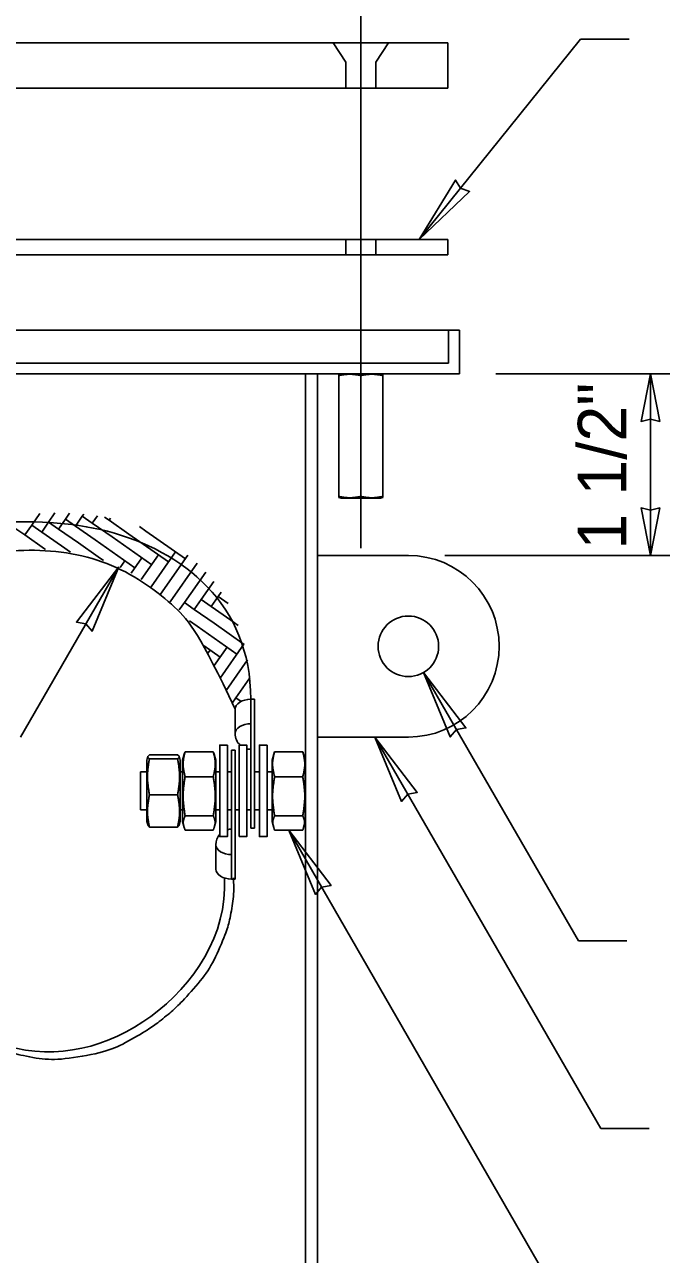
# Model space of a CAD drawing. Extents: x 99862 to 103680, y 99470 to 102076.
# Drawn here: x 100436.1 to 100646.6, y 100208.5 to 100614.8 of the extents above; entities that cross this region are included whole.
import ezdxf

# ---------------------------------------------------------------- set-up
doc = ezdxf.new("R2010")
doc.units = 0
for name, color, linetype in [('Level 1', 7, 'Continuous'), ('Level 10', 7, 'Continuous'), ('Level 11', 7, 'Continuous'), ('Level 13', 7, 'Continuous'), ('Level 15', 7, 'Continuous'), ('Level 16', 7, 'Continuous'), ('Level 2', 7, 'Continuous'), ('Level 20', 7, 'Continuous'), ('Level 6', 7, 'Continuous'), ('Level 9', 7, 'Continuous')]:
    doc.layers.add(name, color=color, linetype=linetype)

msp = doc.modelspace()

# ---------------------------------------------------------------- linework, layer by layer
at = {"layer": 'Level 1'}
for p, q in [((100015.12, 100513.87), (100579.84, 100513.87)), ((100576.28, 100502.97), (100576.28, 100513.87)), ((100579.84, 100499.41), (100579.84, 100513.87)), ((100018.69, 100502.97), (100576.28, 100502.97)), ((100015.12, 100499.41), (100579.84, 100499.41)), ((100528.98, 100139.35), (100528.98, 100499.41)), ((100532.98, 100135.35), (100532.98, 100499.41))]:
    msp.add_line(p, q, dxfattribs=at)
at = {"layer": 'Level 10'}
for p, q in [((100540.75, 100499.41), (100539.99, 100499.2)), ((100540.75, 100499.41), (100539.99, 100499.2)), ((100540.75, 100499.41), (100539.99, 100499.2)), ((100540.75, 100499.41), (100539.99, 100499.2)), ((100539.99, 100458.9), (100539.99, 100498.89)), ((100540.75, 100499.41), (100547.25, 100499.41)), ((100547.25, 100499.41), (100553.75, 100499.41)), ((100547.25, 100458.9), (100547.25, 100498.89)), ((100554.51, 100499.2), (100553.75, 100499.41)), ((100554.51, 100499.2), (100553.75, 100499.41)), ((100554.51, 100499.2), (100553.75, 100499.41)), ((100554.51, 100499.2), (100553.75, 100499.41)), ((100554.51, 100458.9), (100554.51, 100498.89)), ((100539.99, 100458.59), (100540.75, 100458.37)), ((100540.75, 100458.37), (100553.75, 100458.37)), ((100553.75, 100458.37), (100554.51, 100458.59)), ((100476.9, 100373.08), (100476.55, 100371.82)), ((100477.37, 100373.61), (100476.9, 100373.06)), ((100477.37, 100373.61), (100486.71, 100373.61)), ((100477.37, 100372.28), (100486.71, 100372.28)), ((100486.71, 100373.61), (100487.18, 100373.07)), ((100487.53, 100371.82), (100487.18, 100373.08)), ((100488.9, 100373.83), (100488.34, 100371.82)), ((100488.9, 100373.81), (100489.16, 100374.6)), ((100489.16, 100374.6), (100498.5, 100374.6)), ((100498.76, 100373.81), (100498.5, 100374.6)), ((100499.32, 100371.82), (100498.76, 100373.83)), ((100518.48, 100373.83), (100517.92, 100371.81)), ((100518.48, 100373.81), (100518.74, 100374.6)), ((100518.74, 100374.6), (100528.08, 100374.6)), ((100528.34, 100373.81), (100528.08, 100374.6)), ((100528.9, 100371.81), (100528.34, 100373.83)), ((100476.55, 100367.91), (100474.48, 100367.91)), ((100488.34, 100367.91), (100487.53, 100367.91)), ((100500.65, 100367.91), (100499.32, 100367.91)), ((100503.15, 100367.91), (100504.52, 100367.91)), ((100512.19, 100367.91), (100513.76, 100367.91)), ((100516.26, 100367.91), (100517.92, 100367.91)), ((100489.16, 100366.34), (100498.5, 100366.34)), ((100518.74, 100366.34), (100528.08, 100366.34)), ((100477.37, 100360.33), (100486.71, 100360.33)), ((100474.48, 100355.41), (100476.55, 100355.41)), ((100487.53, 100355.41), (100488.34, 100355.41)), ((100499.32, 100355.41), (100500.65, 100355.41)), ((100504.52, 100355.41), (100503.15, 100355.41)), ((100507.07, 100355.41), (100505.77, 100355.41)), ((100510.94, 100355.41), (100509.57, 100355.41)), ((100513.76, 100355.41), (100512.19, 100355.41)), ((100517.92, 100355.41), (100516.26, 100355.41)), ((100476.55, 100351.5), (100476.91, 100350.24)), ((100487.18, 100350.24), (100487.53, 100351.5)), ((100488.34, 100351.5), (100488.9, 100349.5)), ((100489.16, 100353.4), (100498.5, 100353.4)), ((100498.76, 100349.5), (100499.32, 100351.5)), ((100517.92, 100351.5), (100518.48, 100349.5)), ((100518.74, 100353.4), (100528.08, 100353.4)), ((100528.34, 100349.5), (100528.9, 100351.5)), ((100477.37, 100349.7), (100476.9, 100350.25)), ((100477.37, 100349.7), (100486.71, 100349.71)), ((100486.71, 100349.71), (100487.18, 100350.25)), ((100489.16, 100348.72), (100498.5, 100348.72)), ((100518.74, 100348.72), (100528.08, 100348.72))]:
    msp.add_line(p, q, dxfattribs=at)
for centre, major_axis, start_param, end_param in [((100476.55, 100361.66), (0, 10.16), 0.00006, 0.625296), ((100487.53, 100361.66), (0, 10.16), 6.283125, 6.908482), ((100487.53, 100361.66), (0, 10.16), 5.37533, 6.283125), ((100488.34, 100361.66), (0, 10.16), 0.00006, 1.20535), ((100499.32, 100361.66), (0, 10.16), 6.283125, 7.488535), ((100499.32, 100361.66), (0, 10.16), 5.37528, 6.283125), ((100517.92, 100361.66), (0, 10.16), 0.00006, 1.20535), ((100528.9, 100361.66), (0, 10.16), 6.283125, 7.488535), ((100528.9, 100361.66), (0, 10.16), 5.37528, 6.283125), ((100474.48, 100361.66), (0, -6.25), 3.141593, 5.657889), ((100474.48, 100361.66), (0, -6.25), 0, 3.141593), ((100476.55, 100361.66), (0, 10.16), 0.625296, 3.141532), ((100487.53, 100361.66), (0, 10.16), 0.625296, 3.141653), ((100487.53, 100361.66), (0, -6.25), 3.141593, 6.283185), ((100499.32, 100361.66), (0, -6.25), 3.123167, 3.141593), ((100499.32, 100361.66), (0, -6.25), 3.141593, 6.283185), ((100528.9, 100361.66), (0, -6.25), 3.123167, 3.141593), ((100528.9, 100361.66), (0, -6.25), 3.141593, 6.283185), ((100488.34, 100361.66), (0, 10.16), 1.20535, 3.141532), ((100499.32, 100361.66), (0, 10.16), 1.20535, 3.141653), ((100517.92, 100361.66), (0, 10.16), 1.20535, 3.141532), ((100528.9, 100361.66), (0, 10.16), 1.20535, 3.141653), ((100474.48, 100361.66), (0, -6.25), 5.657889, 6.283185), ((100476.55, 100361.66), (0, -6.25), 0, 0.013106), ((100487.53, 100361.66), (0, 10.16), 3.141653, 4.049582), ((100487.53, 100361.66), (0, -6.25), 0, 0.013106), ((100488.34, 100361.66), (0, -6.25), 0, 0.007018), ((100499.32, 100361.66), (0, 10.16), 3.141653, 4.049537), ((100499.32, 100361.66), (0, -6.25), 6.283185, 6.303313), ((100528.9, 100361.66), (0, 10.16), 3.141653, 4.049537), ((100528.9, 100361.66), (0, -6.25), 6.283185, 6.303313)]:
    msp.add_ellipse(centre, major_axis=major_axis, ratio=0.000017, start_param=start_param, end_param=end_param, dxfattribs=at)
for points in [[(100547.25, 100498.89), (100544.83, 100499.31), (100542.41, 100499.3), (100539.99, 100498.89)], [(100539.99, 100498.89), (100539.99, 100498.99), (100539.99, 100499.09), (100539.99, 100499.19)], [(100554.51, 100498.89), (100552.09, 100499.31), (100549.67, 100499.3), (100547.25, 100498.89)], [(100554.51, 100499.2), (100554.51, 100499.09), (100554.51, 100498.99), (100554.51, 100498.89)], [(100539.99, 100458.9), (100539.99, 100458.8), (100539.99, 100458.69), (100539.99, 100458.59)], [(100547.25, 100458.9), (100544.83, 100458.47), (100542.41, 100458.48), (100539.99, 100458.9)], [(100554.51, 100458.9), (100552.09, 100458.47), (100549.67, 100458.48), (100547.25, 100458.9)], [(100554.51, 100458.59), (100554.51, 100458.69), (100554.51, 100458.79), (100554.51, 100458.9)], [(100477.37, 100372.28), (100476.7, 100368.3), (100476.72, 100364.31), (100477.37, 100360.33)], [(100476.9, 100373.06), (100476.8, 100372.8), (100477.08, 100372.54), (100477.37, 100372.28)], [(100487.18, 100373.07), (100487.28, 100372.8), (100487, 100372.54), (100486.71, 100372.28)], [(100486.71, 100372.28), (100487.38, 100368.3), (100487.36, 100364.31), (100486.71, 100360.33)], [(100489.16, 100374.6), (100488.49, 100371.85), (100488.51, 100369.09), (100489.16, 100366.34)], [(100498.5, 100374.6), (100499.17, 100371.85), (100499.15, 100369.1), (100498.5, 100366.34)], [(100518.74, 100374.6), (100518.07, 100371.84), (100518.09, 100369.09), (100518.74, 100366.34)], [(100528.08, 100374.6), (100528.75, 100371.85), (100528.73, 100369.09), (100528.08, 100366.34)], [(100489.16, 100366.34), (100488.49, 100362.03), (100488.51, 100357.72), (100489.16, 100353.4)], [(100498.5, 100366.34), (100499.17, 100362.03), (100499.15, 100357.72), (100498.5, 100353.4)], [(100518.74, 100366.34), (100518.07, 100362.03), (100518.09, 100357.71), (100518.74, 100353.4)], [(100528.08, 100366.34), (100528.75, 100362.03), (100528.73, 100357.71), (100528.08, 100353.4)], [(100477.37, 100360.33), (100476.75, 100356.81), (100476.68, 100353.23), (100477.37, 100349.7)], [(100486.71, 100360.33), (100487.33, 100356.81), (100487.4, 100353.23), (100486.71, 100349.71)], [(100489.16, 100353.4), (100488.64, 100352.11), (100488.49, 100350.81), (100488.9, 100349.51)], [(100498.5, 100353.4), (100499.02, 100352.11), (100499.17, 100350.81), (100498.76, 100349.51)], [(100518.74, 100353.4), (100518.22, 100352.11), (100518.07, 100350.81), (100518.48, 100349.51)], [(100528.08, 100353.4), (100528.6, 100352.11), (100528.75, 100350.81), (100528.34, 100349.51)], [(100488.9, 100349.51), (100488.98, 100349.25), (100489.07, 100348.98), (100489.16, 100348.72)], [(100498.76, 100349.51), (100498.67, 100349.25), (100498.59, 100348.98), (100498.5, 100348.72)], [(100518.48, 100349.51), (100518.57, 100349.24), (100518.65, 100348.98), (100518.74, 100348.72)], [(100528.34, 100349.51), (100528.26, 100349.24), (100528.17, 100348.98), (100528.08, 100348.72)]]:
    msp.add_open_spline(points, degree=2, dxfattribs=at)
at = {"layer": 'Level 11'}
for p, q in [((100441.17, 100453.31), (100438.48, 100449.47)), ((100446.16, 100453.46), (100444.05, 100450.45)), ((100450.99, 100453.38), (100449.62, 100451.43)), ((100455.66, 100453.09), (100455.19, 100452.41)), ((100458.47, 100450.12), (100460.16, 100452.53)), ((100436.19, 100446.19), (100432.91, 100448.48)), ((100436.19, 100446.19), (100438.48, 100449.47)), ((100441.76, 100447.17), (100438.48, 100449.47)), ((100441.76, 100447.17), (100444.05, 100450.45)), ((100447.33, 100448.15), (100444.05, 100450.45)), ((100447.33, 100448.15), (100449.62, 100451.43)), ((100452.9, 100449.14), (100449.62, 100451.43)), ((100452.9, 100449.14), (100455.19, 100452.41)), ((100452.9, 100449.14), (100459.45, 100444.55)), ((100458.47, 100450.12), (100455.19, 100452.41)), ((100458.47, 100450.12), (100465.02, 100445.53)), ((100458.47, 100450.12), (100458.47, 100450.12)), ((100464.04, 100451.1), (100462.57, 100452.13)), ((100464.04, 100451.1), (100464.49, 100451.75)), ((100464.04, 100451.1), (100470.59, 100446.51)), ((100474.09, 100448.94), (100476.16, 100447.49)), ((100436.19, 100446.19), (100442.74, 100441.6)), ((100441.76, 100447.17), (100448.31, 100442.58)), ((100447.33, 100448.15), (100453.88, 100443.57)), ((100472.56, 100435.37), (100459.45, 100444.55)), ((100459.45, 100444.55), (100459.45, 100444.55)), ((100478.13, 100436.35), (100465.02, 100445.53)), ((100483.7, 100437.33), (100470.59, 100446.51)), ((100489.27, 100438.32), (100476.16, 100447.49)), ((100443.06, 100441.37), (100442.74, 100441.6)), ((100451.33, 100440.47), (100448.31, 100442.58)), ((100460.43, 100438.98), (100453.88, 100443.57)), ((100485.99, 100440.61), (100477.92, 100429.08)), ((100462.24, 100437.71), (100460.43, 100438.98)), ((100469.28, 100437.66), (100467.72, 100435.43)), ((100474.85, 100438.65), (100471.29, 100433.56)), ((100480.42, 100439.63), (100474.69, 100431.44)), ((100490.12, 100439.54), (100481.09, 100426.64)), ((100493.13, 100436.85), (100484.19, 100424.09)), ((100495.98, 100433.95), (100488.94, 100423.9)), ((100498.64, 100430.78), (100494.51, 100424.88)), ((100492.22, 100421.6), (100494.51, 100424.88)), ((100497.79, 100422.59), (100494.51, 100424.88)), ((100497.79, 100422.59), (100500.08, 100425.86)), ((100501.12, 100427.35), (100500.08, 100425.86)), ((100503.36, 100423.57), (100500.08, 100425.86)), ((100487.23, 100421.45), (100488.94, 100423.9)), ((100492.22, 100421.6), (100488.94, 100423.9)), ((100492.22, 100421.6), (100498.77, 100417.02)), ((100497.79, 100422.59), (100504.34, 100418)), ((100503.36, 100423.57), (100503.39, 100423.61)), ((100503.36, 100423.57), (100503.45, 100423.51)), ((100490.67, 100417.8), (100493.2, 100416.03)), ((100506.31, 100406.86), (100493.2, 100416.03)), ((100508.73, 100410.04), (100498.77, 100417.02)), ((100506.76, 100416.3), (100504.34, 100418)), ((100500.73, 100405.87), (100495.43, 100409.59)), ((100497.46, 100408.17), (100496.71, 100407.1)), ((100503.03, 100409.15), (100498.74, 100403.02)), ((100508.6, 100410.13), (100500.76, 100398.94)), ((100509.83, 100404.91), (100502.75, 100394.8)), ((100510.57, 100399), (100505.98, 100392.44)), ((100504.73, 100390.66), (100505.98, 100392.44)), ((100507.71, 100391.22), (100505.98, 100392.44))]:
    msp.add_line(p, q, dxfattribs=at)
for points in [[(100510.88, 100391.91), (100510.88, 100423.45), (100465.8, 100458.51), (100384.44, 100444.44), (100299.25, 100431.66), (100238.45, 100476.01), (100238.63, 100499.41)], [(100250.4, 100499.41), (100251.03, 100487.36), (100262.3, 100450.41), (100309.58, 100418.45), (100364.95, 100427.4), (100409.25, 100437.62), (100437.58, 100442.78), (100465.99, 100438.02), (100487.69, 100421.82), (100494.02, 100413.33), (100505.7, 100388.64)]]:
    msp.add_open_spline(points, degree=3, dxfattribs=at)
at = {"layer": 'Level 13'}
for p, q in [((100510.88, 100349.28), (100510.88, 100391.91)), ((100510.88, 100391.91), (100512.13, 100391.91)), ((100512.13, 100391.91), (100512.13, 100349.28)), ((100505.7, 100388.64), (100505.7, 100380.58)), ((100504.52, 100375.15), (100505.77, 100375.15)), ((100504.52, 100367.91), (100504.52, 100374.91)), ((100504.52, 100361.95), (100504.52, 100348.41)), ((100505.77, 100348.41), (100505.77, 100361.95)), ((100504.52, 100349.04), (100504.52, 100351.71)), ((100504.52, 100348.17), (100504.52, 100349.04)), ((100504.52, 100339.05), (100504.52, 100348.17)), ((100510.88, 100349.28), (100512.13, 100349.28)), ((100499.33, 100335.79), (100499.33, 100343.85)), ((100504.52, 100345.19), (100504.52, 100332.52)), ((100505.77, 100332.52), (100505.77, 100345.19)), ((100504.52, 100340.59), (100504.52, 100332.52)), ((100504.52, 100332.52), (100505.77, 100332.52))]:
    msp.add_line(p, q, dxfattribs=at)
for points in [[(100503.15, 100376.76), (100500.65, 100376.76), (100500.65, 100346.55), (100503.15, 100346.55)], [(100507.07, 100346.55), (100509.57, 100346.55), (100509.57, 100376.76), (100507.07, 100376.76)], [(100516.26, 100376.76), (100513.75, 100376.76), (100513.75, 100346.55), (100516.26, 100346.55)]]:
    msp.add_lwpolyline(points, close=True, dxfattribs=at)
for centre, start, end in [((100510.88, 100380.58), 179.9981, 227.372), ((100510.88, 100380.58), 255.3387, 269.9976), ((100504.52, 100343.85), 138.2543, 180.0019), ((100504.52, 100343.85), 90.0024, 105.3086)]:
    msp.add_arc(centre, 5.19, start, end, dxfattribs=at)
for centre, major_axis, ratio, start_param, end_param in [((100510.88, 100388.64), (-5.19, 0), 0.628956, 4.712377, 6.283185), ((100510.88, 100380.58), (5.19, 0), 0.628956, 1.570785, 3.141593), ((100504.52, 100361.66), (0, 13.49), 0.000009, 0, 0.189093), ((100504.52, 100361.66), (0, 13.49), 0.000009, 4.733674, 6.283185), ((100505.77, 100361.66), (0, -13.49), 0.000009, 1.592081, 3.14161), ((100504.52, 100361.66), (0, 6.39), 0.000009, 4.03218, 6.283185), ((100504.52, 100361.66), (0, 6.39), 0.000009, 0, 0.210823), ((100504.52, 100361.66), (0, 6.39), 0.000009, 3.141593, 4.03218), ((100504.52, 100356.52), (0, -6.72), 0.000009, 0.774011, 1.405276), ((100504.52, 100361.66), (0, 6.39), 0.000009, 2.934075, 3.141593), ((100504.52, 100343.85), (0, 5.19), 0.000009, 5.697958, 6.283185), ((100504.52, 100361.66), (0, 13.49), 0.000009, 3.141593, 3.330685), ((100504.52, 100341.6), (0, -6.72), 0.000009, 3.246781, 3.347912), ((100504.52, 100361.66), (0, 13.49), 0.000009, 3.016518, 3.141593), ((100504.52, 100341.6), (0, -6.72), 0.000009, 3.347912, 4.148756), ((100504.52, 100343.85), (0, 5.19), 0.000009, 4.03218, 5.697958), ((100505.77, 100361.66), (0, -13.49), 0.000009, 6.283185, 6.472278), ((100505.77, 100341.6), (0, 6.72), 0.000009, 0.105189, 0.206319), ((100505.77, 100341.6), (0, 6.72), 0.000009, 0.206319, 1.007164), ((100504.52, 100343.85), (5.19, 0), 0.628956, 3.141593, 4.7124), ((100504.52, 100335.79), (-5.19, 0), 0.628956, 6.283185, 7.853993)]:
    msp.add_ellipse(centre, major_axis=major_axis, ratio=ratio, start_param=start_param, end_param=end_param, dxfattribs=at)
at = {"layer": 'Level 15'}
for p, q in [((100547.25, 100664.75), (100547.25, 100441.8)), ((100566.54, 100543.78), (100619.92, 100609.94)), ((100635.92, 100609.94), (100619.92, 100609.94)), ((100591.84, 100499.41), (100660.95, 100499.41)), ((100642.98, 100439.41), (100642.98, 100499.41)), ((100574.98, 100439.41), (100658.98, 100439.41)), ((100467.24, 100435.67), (100434.74, 100379.38)), ((100567.98, 100400.75), (100619.19, 100312.06)), ((100551.89, 100379.41), (100626.57, 100250.07)), ((100523.41, 100348.72), (100631.23, 100161.97)), ((100635.19, 100312.06), (100619.19, 100312.06)), ((100642.57, 100250.07), (100626.57, 100250.07))]:
    msp.add_line(p, q, dxfattribs=at)
for points in [[(100566.54, 100543.78), (100583.2, 100559.68), (100580.22, 100560.73), (100578.56, 100563.43)], [(100642.98, 100499.41), (100639.9, 100483.69), (100642.98, 100484.41), (100646.07, 100483.69)], [(100642.98, 100439.41), (100639.9, 100455.14), (100642.98, 100454.41), (100646.07, 100455.14)], [(100467.24, 100435.67), (100453.24, 100417.39), (100456.35, 100416.81), (100458.41, 100414.4)], [(100567.98, 100400.75), (100581.98, 100382.47), (100578.87, 100381.89), (100576.81, 100379.49)], [(100551.89, 100379.41), (100565.89, 100361.13), (100562.78, 100360.55), (100560.72, 100358.15)], [(100523.41, 100348.72), (100537.41, 100330.44), (100534.3, 100329.86), (100532.24, 100327.45)]]:
    msp.add_lwpolyline(points, close=True, dxfattribs=at)
at = {"layer": 'Level 16'}
for p, q in [((100575.99, 100608.82), (100018.55, 100608.82)), ((100542.25, 100602.38), (100538.1, 100608.83)), ((100552.25, 100602.38), (100556.41, 100608.83)), ((100575.99, 100608.82), (100575.99, 100593.82)), ((100542.25, 100593.82), (100542.25, 100602.38)), ((100552.25, 100593.82), (100552.25, 100602.38)), ((100018.55, 100593.82), (100575.99, 100593.82))]:
    msp.add_line(p, q, dxfattribs=at)
at = {"layer": 'Level 2'}
for p, q in [((100018.55, 100543.78), (100575.99, 100543.78)), ((100542.25, 100538.78), (100542.25, 100543.78)), ((100552.25, 100543.78), (100552.25, 100538.78)), ((100575.99, 100543.78), (100575.99, 100538.78)), ((100575.99, 100538.78), (100018.55, 100538.78))]:
    msp.add_line(p, q, dxfattribs=at)
at = {"layer": 'Level 6'}
for p, q in [((100532.98, 100439.41), (100532.98, 100379.41)), ((100562.98, 100439.41), (100532.98, 100439.41)), ((100532.98, 100379.41), (100562.98, 100379.41))]:
    msp.add_line(p, q, dxfattribs=at)
msp.add_circle((100562.98, 100409.41), 10, dxfattribs=at)
msp.add_arc((100562.98, 100409.41), 30, 270, 90, dxfattribs=at)
at = {"layer": 'Level 9'}
for points in [[(100351.51, 100314.94), (100355.81, 100313.9), (100360.35, 100312.41), (100368.58, 100308.78), (100372.21, 100306.9), (100379.67, 100302.71), (100383.49, 100300.4), (100395.08, 100293.27), (100402.99, 100288.21), (100414.73, 100281.81), (100418.63, 100279.88), (100424.41, 100277.48), (100426.33, 100276.76), (100430.13, 100275.53), (100432.02, 100275.02), (100441.32, 100272.92), (100448.45, 100272.78), (100461.87, 100275.11), (100468.16, 100277.56), (100476.89, 100282.72), (100479.69, 100284.68), (100485.05, 100289.03), (100487.61, 100291.43), (100494.72, 100299.21), (100498.72, 100305.18), (100502.8, 100315.01), (100503.83, 100318.44), (100505.12, 100325.52), (100505.37, 100329.17), (100505.15, 100332.9)], [(100351.99, 100317.91), (100356.53, 100316.82), (100379.84, 100309.22), (100429.98, 100268.56), (100480.67, 100280.92), (100503.25, 100314.16), (100502.15, 100332.72)]]:
    msp.add_open_spline(points, degree=3, dxfattribs=at)

# ---------------------------------------------------------------- texts
at = {"layer": 'Level 20'}
msp.add_text('1 1/2"', height=16, rotation=90, dxfattribs=at).set_placement((100634.98, 100441.32))

doc.saveas('drawing.dxf')
